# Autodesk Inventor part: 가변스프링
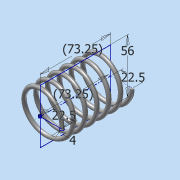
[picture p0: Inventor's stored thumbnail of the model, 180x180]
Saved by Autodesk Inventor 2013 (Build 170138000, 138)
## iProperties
Created: 2018-06
Part Number: 가변스프링
Material: 강철, 연강
Document SubType Name: Modeling
Designer: Administrator
Density: 1 g/cm^3
Mass: -0.137845 g
Surface Area: 106.475 cm^2
Volume: -0.137845 cm^3
Author: Administrator
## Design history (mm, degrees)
sketch "스케치1"
  geometry: L1 (0, 0)-(0, 73.25); L2 (0, 73.25)-(22.5, 73.25); L3 (0, 0)-(22.5, 0); C1 r 2 at (22.5, 0); 1 further point
  constraints: 6 end point, 1 centre point, 1 coincident, 1 parallel, 1 perpendicular, 1 vertical
  dimensions: "d0" = 73.25 distance of L1.start L1.end (derived); "d1" = 22.5 distance of L1.end L2.end; "d2" = 22.5 distance of L1.start L3.end; "d3" = 4 diameter of C1
feature "코일1" sketch "스케치1" pitch "d4" = 10; turns "d6" = 6; dims "d5" = 73.25 (= d0), "d7" = 0, angle "d8" = 90 deg, angle "d9" = 90 deg, "d10" = 0, "d11" = 0
sketch "스케치2"
  geometry: L1 (73.25, 28)-(0, 28); L2 (0, 28)-(0, -28); L3 (0, -28)-(73.25, -28); L4 (73.25, -28)-(73.25, 28); 2 further points
  constraints: 8 end point, 2 parallel, 1 coincident, 1 horizontal, 1 midpoint, 1 perpendicular
  dimensions: "d12" = 73.25 distance of L1.start L1.end (derived); "d14" = 56 distance of L3.end L1.start
extrude "돌출1" sketch "스케치2" stored distance "d15" = 10; taper "d16" = 0 deg
node "솔리드1"
